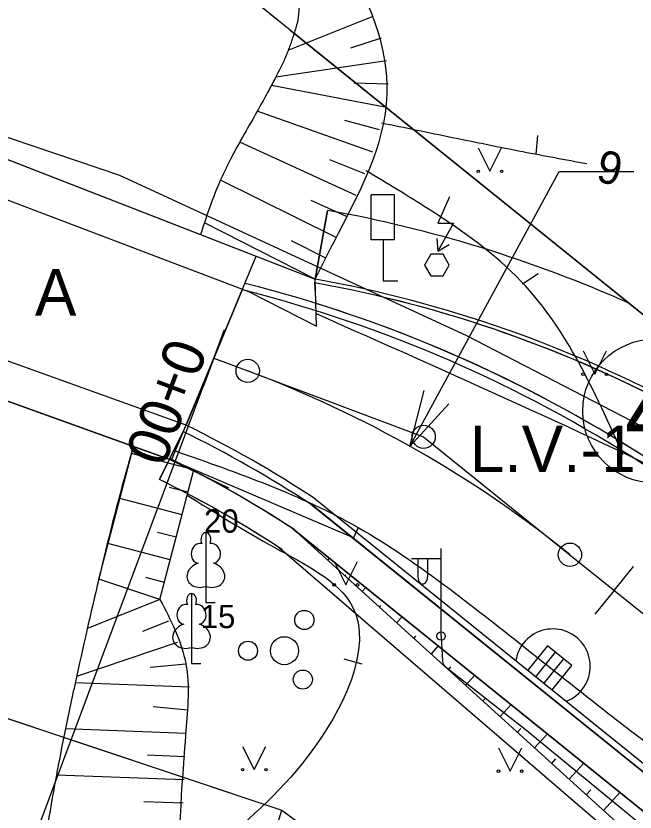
# Model space of a CAD drawing. Extents: x 514086 to 514457, y 297399 to 297567.
# Drawn here: x 514133.42 to 514146.73, y 297486.33 to 297503.43 of the extents above; entities that cross this region are included whole.
import ezdxf

# ---------------------------------------------------------------- set-up
doc = ezdxf.new("R2010")
doc.units = 0
for name, color, linetype in [('AA_Apzimejumi', 7, 'Continuous'), ('AA_Brauktuve', 7, 'Continuous'), ('AA_cela_mala', 7, 'Continuous'), ('AA_Ielas_ass', 7, 'Continuous'), ('AA_Ietve', 7, 'Continuous'), ('AA_izmeri', 7, 'Continuous'), ('AA_nogaze', 7, 'Continuous'), ('AA_Nomale', 7, 'Continuous'), ('AA_vert', 7, 'Continuous'), ('AA_Zale', 7, 'Continuous'), ('Level 1', 7, 'Continuous'), ('Level 12', 7, 'Continuous'), ('Level 16', 7, 'Continuous'), ('Level 23', 7, 'Continuous'), ('Level 29', 7, 'Continuous'), ('Level 31', 7, 'Continuous'), ('Level 32', 7, 'Continuous'), ('Level 36', 7, 'Continuous'), ('Level 37', 7, 'Continuous'), ('Level 41', 7, 'Continuous'), ('Level 42', 7, 'Continuous'), ('Level 44', 7, 'Continuous'), ('Level 45', 7, 'Continuous'), ('Level 46', 7, 'Continuous'), ('Level 8', 7, 'Continuous')]:
    doc.layers.add(name, color=color, linetype=linetype)

msp = doc.modelspace()

# ---------------------------------------------------------------- linework, layer by layer
at = {"layer": 'AA_Apzimejumi'}
msp.add_circle((514147.147, 297494.944), 1.546, dxfattribs=at)
at = {"layer": 'AA_Brauktuve'}
for points in [[(514138.287, 297497.546), (514137.079, 297494.64)], [(514139.852, 297493.058), (514181.234, 297459.714)]]:
    msp.add_lwpolyline(points, dxfattribs=at)
for centre, radius, start, end in [((514131.177, 297469.417), 29.014, 57.1989, 75.8142), ((514125.774, 297471.591), 25.672, 56.7449, 63.8742)]:
    msp.add_arc(centre, radius, start, end, dxfattribs=at)
at = {"layer": 'AA_cela_mala'}
for p, q in [((514139.853, 297497.778), (514139.839, 297497.699)), ((514139.839, 297497.699), (514139.867, 297497.256)), ((514137.079, 297494.64), (514138.287, 297497.546)), ((514139.852, 297493.058), (514181.234, 297459.714)), ((514139.77, 297492.933), (514139.758, 297492.942)), ((514139.758, 297492.942), (514181.14, 297459.597))]:
    msp.add_line(p, q, dxfattribs=at)
for centre, radius, start, end in [((514131.177, 297469.417), 29.164, 57.1989, 75.7708), ((514135.157, 297471.651), 26.465, 61.4692, 79.8096), ((514135.157, 297471.651), 26.545, 61.4692, 79.8096), ((514131.177, 297469.417), 29.014, 57.1989, 75.8142), ((514125.774, 297471.591), 25.672, 56.7449, 63.8742), ((514125.774, 297471.591), 25.522, 56.7449, 63.8742)]:
    msp.add_arc(centre, radius, start, end, dxfattribs=at)
at = {"layer": 'AA_Ielas_ass'}
for p, q in [((514137.676, 297496.077), (514137.907, 297496.694)), ((514129.973, 297475.496), (514137.676, 297496.077)), ((514137.676, 297496.077), (514137.446, 297495.461)), ((514137.676, 297496.077), (514138.404, 297495.805)), ((514138.403, 297495.805), (514142.183, 297494.391)), ((514138.404, 297495.805), (514138.404, 297495.805)), ((514142.183, 297494.391), (514145.326, 297491.858)), ((514145.326, 297491.858), (514156.673, 297482.715)), ((514146.276, 297491.092), (514146.689, 297491.605)), ((514146.276, 297491.092), (514145.864, 297490.58))]:
    msp.add_line(p, q, dxfattribs=at)
for centre in [(514138.403, 297495.805), (514142.183, 297494.391), (514145.326, 297491.858)]:
    msp.add_circle(centre, 0.25, dxfattribs=at)
msp.add_arc((514129.64, 297472.392), 25, 51.1394, 69.4796, dxfattribs=at)
at = {"layer": 'AA_Ietve'}
msp.add_lwpolyline([(514139.839, 297497.699), (514139.867, 297497.256)], dxfattribs=at)
for centre, radius, start, end in [((514135.157, 297471.651), 26.465, 61.4848, 79.8096), ((514131.177, 297469.417), 29.164, 57.1832, 72.6628)]:
    msp.add_arc(centre, radius, start, end, dxfattribs=at)
at = {"layer": 'AA_izmeri'}
for p, q in [((514141.885, 297494.185), (514145.098, 297500.086)), ((514145.098, 297500.086), (514146.698, 297500.086))]:
    msp.add_line(p, q, dxfattribs=at)
msp.add_lwpolyline([(514142.722, 297495.095), (514141.885, 297494.185), (514142.195, 297495.382)], dxfattribs=at)
at = {"layer": 'AA_nogaze'}
for p, q in [((514139.381, 297492.411), (514139.388, 297492.418)), ((514139.751, 297492.075), (514139.757, 297492.081)), ((514140.122, 297491.739), (514140.161, 297491.782)), ((514140.492, 297491.403), (514140.51, 297491.422)), ((514140.862, 297491.067), (514140.941, 297491.154)), ((514141.233, 297490.731), (514141.262, 297490.764)), ((514141.603, 297490.395), (514141.721, 297490.525)), ((514141.973, 297490.059), (514142.015, 297490.105)), ((514142.344, 297489.724), (514142.501, 297489.897)), ((514142.714, 297489.388), (514142.767, 297489.446)), ((514143.084, 297489.052), (514143.281, 297489.268)), ((514143.455, 297488.716), (514143.52, 297488.787)), ((514143.825, 297488.38), (514144.061, 297488.64)), ((514144.196, 297488.044), (514144.272, 297488.128)), ((514144.566, 297487.708), (514144.841, 297488.011)), ((514144.936, 297487.372), (514145.025, 297487.47)), ((514145.307, 297487.036), (514145.621, 297487.383)), ((514145.677, 297486.7), (514145.777, 297486.811)), ((514146.047, 297486.365), (514146.401, 297486.754))]:
    msp.add_line(p, q, dxfattribs=at)
msp.add_lwpolyline([(514139.381, 297492.411), (514153.448, 297479.653), (514157.356, 297476.515), (514190.113, 297451.817)], dxfattribs=at)
at = {"layer": 'AA_Nomale'}
for points in [[(514137.013, 297494.505), (514136.727, 297493.921)], [(514181.14, 297459.597), (514139.77, 297492.933)], [(514139.348, 297492.432), (514139.35, 297492.435), (514139.381, 297492.411)], [(514139.413, 297492.389), (514139.411, 297492.386), (514180.732, 297459.091)]]:
    msp.add_lwpolyline(points, dxfattribs=at)
for radius, start, end in [(25.522, 56.7449, 63.8742), (24.872, 56.9249, 63.8742), (24.872, 56.7449, 56.8344)]:
    msp.add_arc((514125.774, 297471.591), radius, start, end, dxfattribs=at)
at = {"layer": 'AA_vert'}
for p, q in [((514144.595, 297489.236), (514145.018, 297489.762)), ((514144.77, 297489.096), (514145.193, 297489.621))]:
    msp.add_line(p, q, dxfattribs=at)
msp.add_lwpolyline([(514144.42, 297489.378), (514144.946, 297488.955), (514145.369, 297489.48), (514144.844, 297489.904)], close=True, dxfattribs=at)
for start, end in [(291.0464, 142.2118), (142.2118, 171.2324)]:
    msp.add_arc((514144.959, 297489.461), 0.803, start, end, dxfattribs=at)
at = {"layer": 'AA_Zale'}
for p, q in [((514139.853, 297497.778), (514140.118, 297499.254)), ((514146.591, 297497.26), (514175.859, 297473.677)), ((514136.727, 297493.921), (514137.013, 297494.505)), ((514136.506, 297493.472), (514136.727, 297493.921)), ((514139.35, 297492.435), (514180.732, 297459.091))]:
    msp.add_line(p, q, dxfattribs=at)
for points in [[(514140.118, 297499.254), (514139.853, 297497.778)], [(514197.26, 297461.293), (514196.873, 297461.611), (514193.845, 297459.804), (514175.859, 297473.677), (514146.591, 297497.26)], [(514136.727, 297493.921), (514136.506, 297493.472)], [(514180.732, 297459.091), (514139.411, 297492.386), (514139.381, 297492.411)], [(514139.033, 297492.041), (514139.036, 297492.046), (514139.087, 297492.006)], [(514139.036, 297492.046), (514153.448, 297479.653), (514180.419, 297458.702)], [(514139.139, 297491.971), (514139.135, 297491.966), (514153.455, 297479.647), (514180.419, 297458.702)]]:
    msp.add_lwpolyline(points, dxfattribs=at)
for centre, radius, start, end in [((514135.157, 297471.651), 28.045, 65.9378, 79.8096), ((514135.157, 297471.651), 28.045, 65.9378, 79.8096), ((514135.157, 297471.651), 26.545, 61.4692, 79.8096), ((514125.774, 297471.591), 24.872, 56.7449, 63.8742), ((514125.774, 297471.591), 24.872, 56.8344, 63.8742), ((514125.774, 297471.591), 24.372, 56.7449, 63.8742), ((514125.774, 297471.591), 24.372, 57.0433, 63.8742), ((514125.774, 297471.591), 24.372, 56.7449, 56.8926)]:
    msp.add_arc(centre, radius, start, end, dxfattribs=at)
at = {"layer": 'Level 1'}
for p, q in [((514137.504, 297491.178), (514137.504, 297490.831)), ((514137.504, 297490.831), (514137.704, 297490.831)), ((514137.196, 297489.868), (514137.196, 297489.521)), ((514137.196, 297489.521), (514137.396, 297489.521))]:
    msp.add_line(p, q, dxfattribs=at)
for points in [[(514137.504, 297492.331), (514137.504, 297491.178)], [(514137.594, 297492.099), (514137.593, 297492.1)], [(514137.196, 297491.021), (514137.196, 297489.868)], [(514137.286, 297490.789), (514137.285, 297490.79)]]:
    msp.add_lwpolyline(points, dxfattribs=at)
for centre, radius in [((514139.62, 297490.456), 0.207), ((514138.409, 297489.796), 0.204), ((514139.193, 297489.796), 0.301), ((514139.588, 297489.176), 0.205)]:
    msp.add_circle(centre, radius, dxfattribs=at)
for centre, major_axis, ratio, start_param, end_param in [((514137.504, 297492.181), (0, -0.15), 0.707107, 3.14537, 5.287485), ((514137.504, 297492.181), (0, -0.15), 0.707107, 0.995701, 3.137816), ((514137.376, 297491.886), (-0.039, -0.212), 0.861323, 3.141593, 6.283185), ((514137.632, 297491.886), (0.039, -0.212), 0.861323, 0, 3.141593), ((514137.414, 297491.424), (0.307, 0.095), 0.814445, 1.570796, 4.752015), ((514137.594, 297491.424), (-0.307, 0.095), 0.814445, 1.531171, 4.712389), ((514137.196, 297490.871), (0, -0.15), 0.707107, 3.14537, 5.287485), ((514137.196, 297490.871), (0, -0.15), 0.707107, 0.995701, 3.137816), ((514137.068, 297490.576), (-0.039, -0.212), 0.861323, 3.141593, 6.283185), ((514137.324, 297490.576), (0.039, -0.212), 0.861323, 0, 3.141593), ((514137.106, 297490.114), (0.307, 0.095), 0.814445, 1.570796, 4.752015), ((514137.286, 297490.114), (-0.307, 0.095), 0.814445, 1.531171, 4.712389)]:
    msp.add_ellipse(centre, major_axis=major_axis, ratio=ratio, start_param=start_param, end_param=end_param, dxfattribs=at)
at = {"layer": 'Level 12'}
msp.add_line((514142.49, 297498.379), (514142.731, 297498.518), dxfattribs=at)
for points in [[(514142.739, 297499.541), (514142.49, 297498.978), (514142.826, 297498.978), (514142.49, 297498.379)], [(514142.468, 297498.649), (514142.49, 297498.379)]]:
    msp.add_lwpolyline(points, dxfattribs=at)
msp.add_lwpolyline([(514142.334, 297497.849), (514142.6, 297497.849), (514142.733, 297498.079), (514142.6, 297498.31), (514142.334, 297498.31), (514142.201, 297498.079)], close=True, dxfattribs=at)
at = {"layer": 'Level 16'}
for p, q in [((514141.558, 297499.589), (514141.058, 297499.589)), ((514141.058, 297498.62), (514141.058, 297499.589)), ((514141.558, 297498.62), (514141.558, 297499.589)), ((514141.558, 297498.62), (514141.058, 297498.62)), ((514141.312, 297498.62), (514141.312, 297497.742)), ((514141.312, 297497.742), (514141.627, 297497.742))]:
    msp.add_line(p, q, dxfattribs=at)
at = {"layer": 'Level 23'}
for p, q in [((514143.357, 297500.593), (514143.607, 297500.093)), ((514143.607, 297500.093), (514143.857, 297500.593)), ((514145.612, 297496.235), (514145.862, 297495.735)), ((514145.862, 297495.735), (514146.112, 297496.235)), ((514140.262, 297491.71), (514140.512, 297491.21)), ((514140.512, 297491.21), (514140.762, 297491.71)), ((514138.294, 297487.741), (514138.544, 297487.241)), ((514138.544, 297487.241), (514138.794, 297487.741)), ((514143.791, 297487.71), (514144.041, 297487.21)), ((514144.041, 297487.21), (514144.291, 297487.71))]:
    msp.add_line(p, q, dxfattribs=at)
for centre, radius in [((514143.357, 297500.092), 0.028), ((514143.857, 297500.092), 0.0263), ((514145.611, 297495.734), 0.028), ((514146.111, 297495.734), 0.0263), ((514140.262, 297491.21), 0.028), ((514140.762, 297491.21), 0.0263), ((514138.294, 297487.241), 0.028), ((514138.794, 297487.241), 0.0263), ((514143.791, 297487.209), 0.028), ((514144.291, 297487.209), 0.0263)]:
    msp.add_circle(centre, radius, dxfattribs=at)
at = {"layer": 'Level 29'}
for p, q in [((514139.316, 297503.122), (514133.046, 297508.174)), ((514139.316, 297503.122), (514175.859, 297473.677)), ((514130.604, 297489.221), (514139.134, 297486.37)), ((514135.213, 297473.203), (514139.134, 297486.37)), ((514139.134, 297486.37), (514229.261, 297420.493))]:
    msp.add_line(p, q, dxfattribs=at)
at = {"layer": 'Level 31'}
for p, q in [((514141.092, 297503.417), (514139.266, 297502.685)), ((514141.27, 297502.95), (514140.609, 297502.737)), ((514141.387, 297502.464), (514139.006, 297502.117)), ((514141.349, 297501.472), (514138.913, 297501.935)), ((514141.421, 297501.967), (514140.682, 297501.982)), ((514141.091, 297500.507), (514138.604, 297501.384)), ((514141.235, 297500.986), (514140.487, 297501.18)), ((514140.73, 297499.575), (514138.23, 297500.716)), ((514140.919, 297500.038), (514140.168, 297500.34)), ((514140.305, 297498.67), (514137.816, 297499.905)), ((514140.522, 297499.12), (514139.764, 297499.466)), ((514139.853, 297497.778), (514137.475, 297498.987)), ((514140.08, 297498.224), (514139.347, 297498.596)), ((514136.518, 297490.897), (514134.961, 297490.272)), ((514136.704, 297490.433), (514136.141, 297490.207)), ((514136.89, 297489.969), (514134.727, 297489.241)), ((514137.076, 297489.505), (514136.309, 297489.435)), ((514137.155, 297489.014), (514134.698, 297489.108)), ((514137.118, 297488.516), (514136.37, 297488.591)), ((514137.071, 297488.018), (514134.487, 297488.116)), ((514137.052, 297487.518), (514136.253, 297487.549)), ((514137.034, 297487.019), (514134.292, 297487.122)), ((514137.015, 297486.519), (514136.172, 297486.551))]:
    msp.add_line(p, q, dxfattribs=at)
for points in [[(514139.853, 297497.778), (514140.258, 297498.576), (514141.401, 297501.745), (514140.437, 297504.714), (514138.22, 297507.891), (514137.927, 297508.692), (514139.101, 297511.202), (514139.369, 297511.596)], [(514136.518, 297490.897), (514137.074, 297489.513), (514137.074, 297488.075), (514136.798, 297480.788)]]:
    msp.add_spline(points, degree=3, dxfattribs=at)
at = {"layer": 'Level 32'}
for p, q in [((514144.602, 297500.461), (514144.638, 297500.859)), ((514144.31, 297497.676), (514144.642, 297497.899)), ((514140.859, 297489.506), (514140.474, 297489.615))]:
    msp.add_line(p, q, dxfattribs=at)
for points in [[(514141.277, 297501.135), (514142.796, 297500.822), (514144.316, 297500.516), (514145.691, 297500.258)], [(514146.466, 297494.001), (514144.28, 297497.727), (514142.28, 297499.286), (514140.947, 297500.103)], [(514137.103, 297493.136), (514138.988, 297492.009), (514140.65, 297490.75), (514139.702, 297487.535), (514137.621, 297485.453), (514136.95, 297484.807)]]:
    msp.add_spline(points, degree=3, dxfattribs=at)
at = {"layer": 'Level 36'}
for points in [[(514138.109, 297512.063), (514137.564, 297511.301), (514137.455, 297511.127), (514137.365, 297510.942), (514137.294, 297510.748), (514137.238, 297510.546), (514137.169, 297510.117), (514137.16, 297509.688), (514137.226, 297508.808), (514137.281, 297508.385), (514137.333, 297507.988), (514137.505, 297507.371), (514137.643, 297507.078), (514137.803, 297506.795), (514138.001, 297506.491), (514138.209, 297506.197), (514138.418, 297505.904), (514138.619, 297505.606), (514138.984, 297505.024), (514139.157, 297504.727), (514139.322, 297504.419), (514139.43, 297504.13), (514139.463, 297503.98), (514139.488, 297503.828), (514139.5, 297503.533), (514139.454, 297503.238), (514139.378, 297502.987), (514139.293, 297502.742), (514139.196, 297502.503), (514139.084, 297502.27), (514138.565, 297501.307), (514138.028, 297500.342), (514137.601, 297499.365), (514137.39, 297498.735)], [(514135.944, 297494.184), (514135.826, 297493.769), (514135.201, 297491.331), (514134.701, 297489.124), (514134.467, 297488.021), (514134.358, 297487.468), (514134.253, 297486.913), (514133.928, 297484.691), (514133.806, 297482.455), (514133.806, 297481.042)]]:
    msp.add_spline(points, degree=3, dxfattribs=at)
at = {"layer": 'Level 37'}
for points in [[(514126.706, 297502.049), (514132.533, 297499.744), (514138.422, 297497.512)], [(514137.079, 297494.64), (514125.373, 297498.844)], [(514138.586, 297498.267), (514139.853, 297497.778)], [(514136.731, 297493.901), (514125.059, 297498.1)], [(514138.422, 297497.512), (514139.881, 297496.766), (514139.853, 297497.778)], [(514140.775, 297492.444), (514140.678, 297492.223), (514136.767, 297493.888)]]:
    msp.add_lwpolyline(points, dxfattribs=at)
for points in [[(514139.874, 297497.035), (514148.452, 297493.087), (514152.9, 297490.654), (514155.012, 297489.24), (514157.055, 297487.727), (514160.163, 297485.252), (514163.225, 297482.729), (514166.288, 297480.21), (514169.399, 297477.75), (514184.679, 297466.049), (514188.685, 297462.979), (514190.692, 297461.445), (514192.708, 297459.912), (514193.134, 297459.688), (514193.613, 297459.574), (514194.114, 297459.524), (514194.606, 297459.489), (514195.045, 297459.442), (514195.506, 297459.417), (514195.979, 297459.548), (514196.259, 297459.707)], [(514136.849, 297494.086), (514140.775, 297492.444), (514142.699, 297491.153), (514143.967, 297490.173), (514145.225, 297489.179), (514146.485, 297488.19), (514147.764, 297487.226), (514149.635, 297485.885), (514151.52, 297484.563), (514153.402, 297483.236), (514155.263, 297481.88), (514159.161, 297478.934), (514163.043, 297475.965), (514166.923, 297472.996), (514170.82, 297470.048), (514173.26, 297468.237), (514175.709, 297466.438), (514178.159, 297464.639), (514180.6, 297462.828), (514184.429, 297459.874), (514186.323, 297458.371), (514188.215, 297456.863), (514189.034, 297456.154), (514191.11, 297453.709)]]:
    msp.add_spline(points, degree=3, dxfattribs=at)
at = {"layer": 'Level 41'}
for p, q in [((514127.006, 297502.771), (514138.586, 297498.267)), ((514136.767, 297493.888), (514138.586, 297498.267)), ((514137.245, 297493.682), (514135.908, 297494.031)), ((514136.518, 297490.897), (514137.245, 297493.682)), ((514137.119, 297493.198), (514136.717, 297493.303)), ((514136.993, 297492.714), (514135.654, 297493.064)), ((514136.866, 297492.231), (514136.465, 297492.335)), ((514136.74, 297491.747), (514135.401, 297492.096)), ((514136.614, 297491.263), (514136.212, 297491.368))]:
    msp.add_line(p, q, dxfattribs=at)
for points in [[(514125.064, 297498.098), (514136.767, 297493.888)], [(514136.518, 297490.897), (514135.201, 297491.331), (514135.947, 297494.183)]]:
    msp.add_lwpolyline(points, dxfattribs=at)
at = {"layer": 'Level 42'}
for p, q in [((514125.064, 297498.099), (514136.731, 297493.901)), ((514136.731, 297493.901), (514137.993, 297493.292))]:
    msp.add_line(p, q, dxfattribs=at)
msp.add_lwpolyline([(514124.758, 297503.876), (514126.998, 297502.774), (514139.853, 297497.778)], dxfattribs=at)
at = {"layer": 'Level 44'}
for p, q in [((514142.558, 297490.109), (514142.558, 297491.992)), ((514142.558, 297491.772), (514141.923, 297491.772)), ((514142.058, 297491.772), (514142.058, 297491.38)), ((514142.268, 297491.772), (514142.268, 297491.38))]:
    msp.add_line(p, q, dxfattribs=at)
msp.add_circle((514142.558, 297490.109), 0.09, dxfattribs=at)
msp.add_ellipse((514142.163, 297491.38), major_axis=(0, 0.151), ratio=0.695971, start_param=1.570796, end_param=4.712389, dxfattribs=at)
at = {"layer": 'Level 45'}
for points in [[(514142.558, 297490.109), (514142.588, 297489.565)], [(514142.645, 297489.455), (514144.367, 297488.114), (514148.432, 297484.764), (514152.497, 297481.414), (514158.438, 297477.231), (514164.38, 297473.048), (514165.491, 297472.425)]]:
    msp.add_lwpolyline(points, dxfattribs=at)
msp.add_arc((514142.737, 297489.573), 0.15, 183.1119, 232.0938, dxfattribs=at)
at = {"layer": 'Level 46'}
msp.add_lwpolyline([(514139.134, 297486.37), (514229.261, 297420.493), (514237.863, 297414.208), (514250.009, 297428.181), (514295.433, 297494.723), (514312.775, 297524.542), (514316.491, 297528.738), (514320.446, 297531.016), (514328.236, 297532.215), (514332.539, 297530.572), (514332.631, 297530.536), (514341.642, 297542.18), (514320.211, 297553.997), (514285.885, 297496.27), (514243.195, 297433.696), (514241.534, 297432.407), (514239.451, 297432.203), (514209.969, 297445.237), (514194.45, 297457.413), (514175.859, 297473.677), (514139.316, 297503.122), (514133.046, 297508.174), (514130.604, 297489.221)], close=True, dxfattribs=at)
at = {"layer": 'Level 8'}
msp.add_lwpolyline([(514200.623, 297456.189), (514178.139, 297473.151), (514155.647, 297490.079), (514143.111, 297496.557), (514135.656, 297500), (514119.377, 297505.512), (514108.036, 297513.213), (514096.037, 297522.278)], dxfattribs=at)

# ---------------------------------------------------------------- texts
at = {"layer": 'AA_Apzimejumi'}
msp.add_text('4', height=1.5, dxfattribs=at).set_placement((514146.508, 297494.168))
at = {"layer": 'AA_Ielas_ass'}
for s, height, rotation, p in [(' 0+00', 0.9, 249.4798, (514136.826, 297496.882)), ('L.V.-1', 1, 360, (514143.174, 297493.631))]:
    msp.add_text(s, height=height, rotation=rotation, dxfattribs=at).set_placement(p)
at = {"layer": 'Level 1'}
for s, p in [(' 20', (514137.279, 297492.331)), (' 15', (514137.208, 297490.28))]:
    msp.add_text(s, height=0.5, dxfattribs=at).set_placement(p)
at = {"layer": 'Level 32'}
msp.add_text('6', height=0.7, rotation=168.626, dxfattribs=at).set_placement((514146.51, 297500.46))
at = {"layer": 'Level 37'}
msp.add_text('A', height=1, dxfattribs=at).set_placement((514133.831, 297496.992))

doc.saveas('drawing.dxf')
